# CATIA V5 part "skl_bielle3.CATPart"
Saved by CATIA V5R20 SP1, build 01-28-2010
Part number: skl_bielle3
Publications: "Plan_ref", "PointE", "Plan_pivot_E", "Point_projete", "Point_pivot_avec_coulisseau", "axe_pivot_Pt_E", "axe_pivot_Pt_projete", "axe_ref", "Plan_decalage_epaisseur"
Bounding box of the stored display mesh (mm): x -40 to 40, y 0 to 250, z 0 to 30
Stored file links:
  C:\Users\Fabien-port\Desktop\test\skl_bielle3.CATPart
  C:\Users\Fabien-port\Desktop\test\ass_skl_mecanisme_a_coulisseau.CATProduct
  C:\Users\Fabien-port\Desktop\test\mecanisme_a_coulisseau.CATProduct
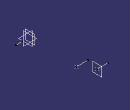
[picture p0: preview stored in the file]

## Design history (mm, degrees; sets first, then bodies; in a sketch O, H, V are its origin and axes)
External parameters (linked from other documents)
  External.epaisseur_bielle = 8 mm
Set1
  Plane1 "Plan_ref": linked copy from another document
  Point1 "PointE": linked copy from another document
  Point2 "Point_projete": linked copy from another document
  Line1 "axe_ref": linked copy from another document
Set2
  Plane2 "Plan_pivot_E": type OffsetPt, RefPlane Plane1, RefPoint Point1
  Point3 "Point_pivot_avec_coulisseau": (0, 0, 0), relative to Point2
  Line2 "axe_pivot_Pt_projete": type PtDir, RefPoint Point3, Direction Line1, Start 0, End 40
  Line3 "axe_pivot_Pt_E": type PtDir, RefPoint Point1, Direction Line1, Start 0, End 40
  Plane3 "Plan_decalage_epaisseur": type Offset, RefPlane Plane1, Offset 9 {= External.epaisseur_bielle +1mm}, reversed
Body1 (main body)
